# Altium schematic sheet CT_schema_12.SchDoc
size 278 x 170 mm
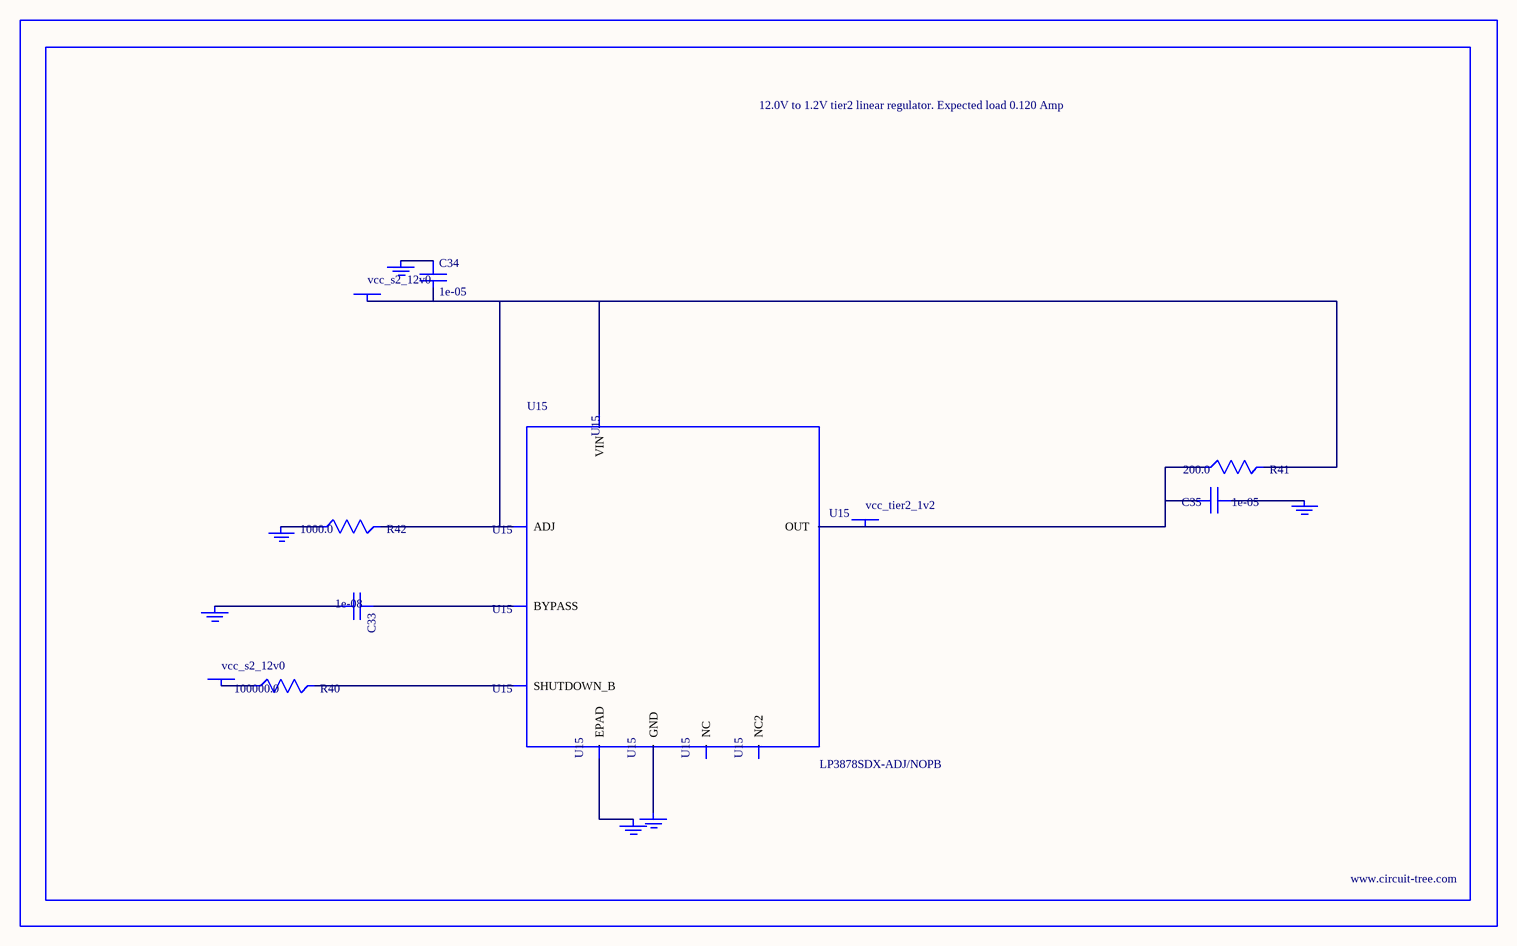
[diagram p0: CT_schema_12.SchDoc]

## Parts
BORDER11  (no value)
C33  1e-08  [C0402]
C34  1e-05  [C1210]
C35  1e-05  [C0805]
GND_INSTANCE_11_0  (no value)
GND_INSTANCE_11_1  (no value)
GND_INSTANCE_11_2  (no value)
GND_INSTANCE_11_3  (no value)
GND_INSTANCE_11_4  (no value)
GND_INSTANCE_11_5  (no value)
POWER_INSTANCE_11_0  vcc_s2_12v0
POWER_INSTANCE_11_1  vcc_s2_12v0
POWER_INSTANCE_11_2  vcc_tier2_1v2
R40  100000.0  [R0603]
R41  200.0  [R0603]
R42  1000.0  [R0603]
U15  LP3878SDX-ADJ/NOPB  [WSON-8]

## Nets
NetC33_1: C33.1 U15.1(BYPASS)
NetC33_2: C33.2 GND_INSTANCE_11_0.0(GND)
NetC34_1: C34.1 GND_INSTANCE_11_1.0(GND)
NetC34_2: C34.2 POWER_INSTANCE_11_0.0(PWR) R41.2 R42.2 U15.4(VIN) U15.6(ADJ)
NetC35_1: C35.1 GND_INSTANCE_11_2.0(GND)
NetC35_2: C35.2 POWER_INSTANCE_11_2.0(PWR) R41.1 U15.5(OUT)
NetGND_INSTANCE_11_3_0: GND_INSTANCE_11_3.0(GND) R42.1
NetGND_INSTANCE_11_4_0: GND_INSTANCE_11_4.0(GND) U15.PAD(EPAD)
NetGND_INSTANCE_11_5_0: GND_INSTANCE_11_5.0(GND) U15.3(GND)
NetPOWER_INSTANCE_11_1_0: POWER_INSTANCE_11_1.0(PWR) R40.1
NetR40_2: R40.2 U15.8(SHUTDOWN_B)

Not connected (* = marked no-connect by the designer): U15 2(NC) 7(NC2)

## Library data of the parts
BORDER11 = BORDER_PAGE11
C33 = C0402C103K3RAC
C34 = C1210C106K5PACTU
C35 = GRM219R60J106ME19D
GND_INSTANCE_11_0-GND_INSTANCE_11_5 = GND
POWER_INSTANCE_11_0-POWER_INSTANCE_11_2 = PWR
R40 = RC0603JR-07100KL
R41 = RC0603JR-07200RL
R42 = RC0603JR-071KL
